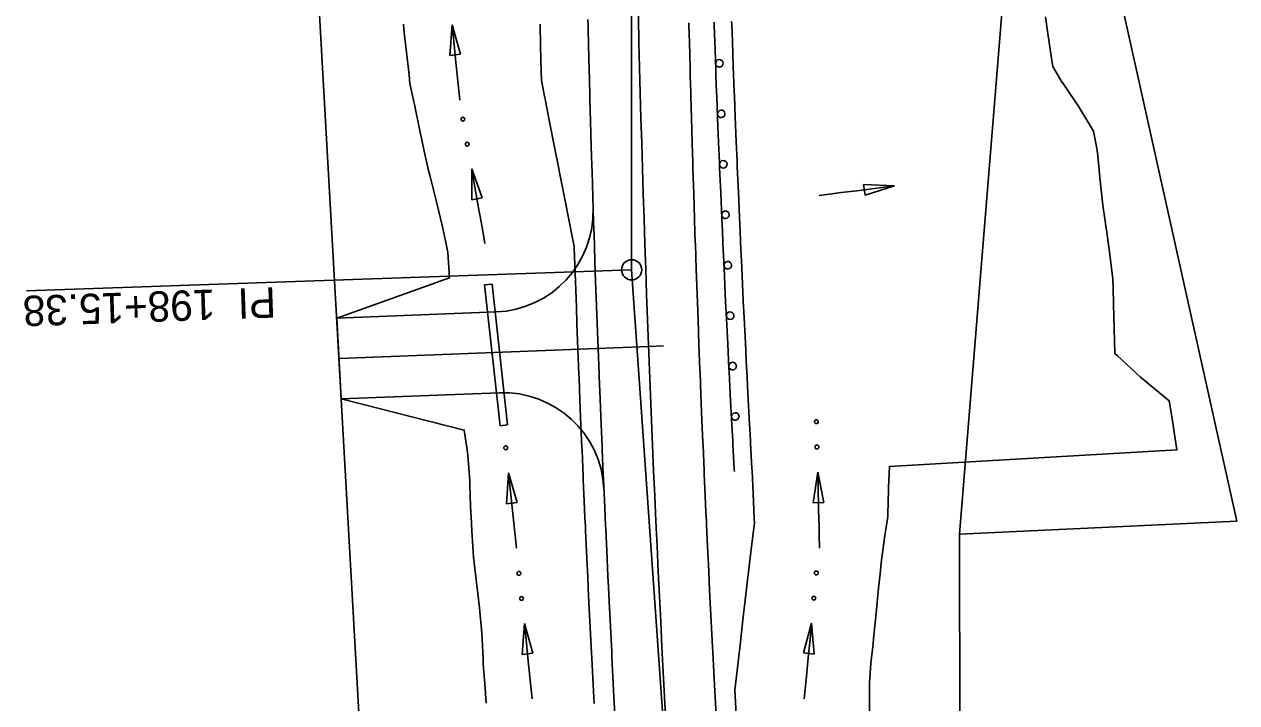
# Model space of a CAD drawing. Extents: x 1 to 1477871, y 1 to 1872901.
# Drawn here: x 1438490.8 to 1438731.1, y 1869665.9 to 1869800.2 of the extents above; entities that cross this region are included whole.
import ezdxf

# ---------------------------------------------------------------- set-up
doc = ezdxf.new("R2010")
doc.units = 0
for name, color, linetype in [('R_Drive', 7, 'Continuous'), ('R_Horz Alg', 7, 'Continuous'), ('R_Horz Alg Annot', 7, 'Continuous'), ('R_No Plot', 7, 'Continuous'), ('R_Proposed Const Limits_Cut', 7, 'Continuous'), ('R_Proposed Road_Lane', 7, 'Continuous'), ('R_Proposed Road_Shoulder', 7, 'Continuous'), ('R_ROW', 7, 'Continuous'), ('R_Steel', 7, 'Continuous'), ('R_Temp Easement', 7, 'Continuous'), ('R_Water', 7, 'Continuous')]:
    doc.layers.add(name, color=color, linetype=linetype)

msp = doc.modelspace()

# ---------------------------------------------------------------- linework, layer by layer
at = {"layer": 'R_Drive'}
for p, q in [((1438552.73, 1869742.04), (1438584.34, 1869743.25)), ((1438552.73, 1869742.04), (1438553.63, 1869726.06)), ((1438553.63, 1869726.06), (1438584.94, 1869727.26))]:
    msp.add_line(p, q, dxfattribs=at)
for centre, start, end in [((1438583.57, 1869763.23), 272.1875, 1.841), ((1438585.71, 1869707.27), 2.473, 92.1875)]:
    msp.add_arc(centre, 20, start, end, dxfattribs=at)
at = {"layer": 'R_Horz Alg'}
msp.add_arc((1443194.86, 1869911.35), 4583.66, 180, 183.99213, dxfattribs=at)
at = {"layer": 'R_Horz Alg Annot'}
for p, q in [((1438611.19, 1869751.6), (1438611.19, 1869911.35)), ((1438622.32, 1869592.24), (1438611.19, 1869751.6))]:
    msp.add_line(p, q, dxfattribs=at)
for points in [[(1438611.19, 1869751.6), (1438491.27, 1869747.42)], [(1438617.53, 1869736.51), (1438614.53, 1869736.4)]]:
    msp.add_lwpolyline(points, dxfattribs=at)
msp.add_circle((1438611.19, 1869751.6), 2, dxfattribs=at)
at = {"layer": 'R_No Plot'}
msp.add_line((1438553.26, 1869734.05), (1438614.53, 1869736.4), dxfattribs=at)
at = {"layer": 'R_Proposed Const Limits_Cut'}
for points in [[(1438658.35, 1869663.74), (1438658.32, 1869668.64), (1438658.3, 1869669.81), (1438658.62, 1869673.62), (1438659.03, 1869677.55), (1438659.15, 1869678.61), (1438659.65, 1869683.59), (1438660.13, 1869688.58), (1438660.43, 1869691.4), (1438660.66, 1869693.56), (1438661.31, 1869698.55), (1438661.93, 1869702.72), (1438661.95, 1869703.53), (1438662.01, 1869705.24), (1438662.12, 1869708.5), (1438662.26, 1869712.64), (1438719.25, 1869715.94), (1438718.53, 1869720.8), (1438718.43, 1869721.39), (1438717.73, 1869725.66), (1438712.06, 1869730.32), (1438707.46, 1869734.54), (1438706.94, 1869735.02), (1438706.84, 1869739.92), (1438706.71, 1869744.82), (1438706.62, 1869748.12), (1438706.57, 1869749.72), (1438705.97, 1869754.6), (1438705.27, 1869759.48), (1438705.23, 1869759.79), (1438704.96, 1869761.68), (1438704.58, 1869764.36), (1438704.02, 1869769.24), (1438703.55, 1869774.13), (1438703.45, 1869775.25), (1438702.71, 1869779.01), (1438699.84, 1869783.83), (1438697.1, 1869787.86), (1438696.56, 1869788.65), (1438696.54, 1869788.68), (1438694.66, 1869791.86), (1438694.38, 1869793.5), (1438693.68, 1869798.4), (1438693.21, 1869801.65)], [(1438582.38, 1869665.77), (1438582.07, 1869669.61), (1438581.79, 1869673.57), (1438581.73, 1869674.64), (1438581.47, 1869679.67), (1438581.02, 1869684.69), (1438580.73, 1869687.53), (1438580.46, 1869689.71), (1438579.82, 1869694.72), (1438579.58, 1869698.93), (1438579.53, 1869699.75), (1438579.43, 1869701.48), (1438579.24, 1869704.79), (1438579.11, 1869709), (1438579.09, 1869709.82), (1438578.71, 1869714.85), (1438578.64, 1869715.46), (1438578.02, 1869719.87), (1438553.63, 1869726.06), (1438552.73, 1869742.04), (1438575.09, 1869750.03), (1438574.76, 1869755.06), (1438574.72, 1869755.38), (1438574.29, 1869757.32), (1438573.67, 1869760.07), (1438572.51, 1869765.08), (1438571.25, 1869770.09), (1438570.96, 1869771.23), (1438570.1, 1869775.1), (1438569.02, 1869780.12), (1438568.13, 1869784.32), (1438567.95, 1869785.14), (1438567.95, 1869785.17), (1438567.25, 1869788.48), (1438567.07, 1869790.17), (1438566.5, 1869795.21), (1438566.13, 1869798.55), (1438566.07, 1869799.15), (1438565.97, 1869800.25)]]:
    msp.add_lwpolyline(points, dxfattribs=at)
at = {"layer": 'R_Proposed Road_Lane'}
for points in [[(1438608.02, 1869660.99), (1438607.75, 1869665.94), (1438607.69, 1869667.12), (1438607.49, 1869670.94), (1438607.28, 1869674.89), (1438607.23, 1869675.94), (1438606.98, 1869680.95), (1438606.73, 1869685.95), (1438606.59, 1869688.79), (1438606.48, 1869690.96), (1438606.25, 1869695.96), (1438606.05, 1869700.15), (1438606.01, 1869700.97), (1438605.94, 1869702.69), (1438605.79, 1869705.97), (1438605.6, 1869710.16), (1438605.57, 1869710.98), (1438605.35, 1869715.99), (1438605.32, 1869716.59), (1438605.14, 1869720.99), (1438604.94, 1869726), (1438604.76, 1869730.49), (1438604.74, 1869731.01), (1438604.54, 1869736.01), (1438604.35, 1869741.02), (1438604.23, 1869744.4), (1438604.17, 1869746.03), (1438603.99, 1869751.04), (1438603.82, 1869756.04), (1438603.81, 1869756.36), (1438603.74, 1869758.31), (1438603.65, 1869761.05), (1438603.49, 1869766.06), (1438603.34, 1869771.07), (1438603.3, 1869772.21), (1438603.19, 1869776.08), (1438603.04, 1869781.09), (1438602.92, 1869785.27), (1438602.9, 1869786.1), (1438602.9, 1869786.12), (1438602.81, 1869789.42), (1438602.77, 1869791.1), (1438602.64, 1869796.11), (1438602.56, 1869799.44), (1438602.54, 1869800.04), (1438602.52, 1869801.12)], [(1438627.99, 1869662.08), (1438627.73, 1869667), (1438627.66, 1869668.18), (1438627.46, 1869671.99), (1438627.26, 1869675.92), (1438627.2, 1869676.97), (1438626.95, 1869681.95), (1438626.7, 1869686.93), (1438626.56, 1869689.75), (1438626.46, 1869691.92), (1438626.22, 1869696.9), (1438626.03, 1869701.07), (1438625.99, 1869701.88), (1438625.92, 1869703.59), (1438625.77, 1869706.87), (1438625.58, 1869711.04), (1438625.55, 1869711.85), (1438625.33, 1869716.84), (1438625.31, 1869717.44), (1438625.12, 1869721.82), (1438624.92, 1869726.81), (1438624.74, 1869731.28), (1438624.72, 1869731.79), (1438624.53, 1869736.78), (1438624.34, 1869741.76), (1438624.22, 1869745.12), (1438624.16, 1869746.75), (1438623.98, 1869751.73), (1438623.81, 1869756.72), (1438623.8, 1869757.04), (1438623.73, 1869758.97), (1438623.64, 1869761.71), (1438623.48, 1869766.69), (1438623.33, 1869771.68), (1438623.29, 1869772.82), (1438623.18, 1869776.67), (1438623.03, 1869781.65), (1438622.92, 1869785.82), (1438622.89, 1869786.64), (1438622.89, 1869786.67), (1438622.8, 1869789.95), (1438622.76, 1869791.63), (1438622.63, 1869796.62), (1438622.55, 1869799.93), (1438622.54, 1869800.52)]]:
    msp.add_lwpolyline(points, dxfattribs=at)
at = {"layer": 'R_Proposed Road_Shoulder'}
for points in [[(1438603.76, 1869665.72), (1438603.7, 1869666.9), (1438603.5, 1869670.73), (1438603.29, 1869674.68), (1438603.24, 1869675.74), (1438602.98, 1869680.75), (1438602.73, 1869685.76), (1438602.59, 1869688.59), (1438602.49, 1869690.77), (1438602.25, 1869695.78), (1438602.06, 1869699.96), (1438602.02, 1869700.79), (1438601.94, 1869702.5), (1438601.79, 1869705.79), (1438601.61, 1869709.98), (1438601.57, 1869710.8), (1438601.35, 1869715.82), (1438601.33, 1869716.42), (1438601.14, 1869720.83), (1438600.94, 1869725.84), (1438600.76, 1869730.33), (1438600.74, 1869730.85), (1438600.54, 1869735.86), (1438600.35, 1869740.87), (1438600.23, 1869744.25), (1438600.17, 1869745.88), (1438599.99, 1869750.9), (1438599.82, 1869755.91), (1438599.81, 1869756.23), (1438599.42, 1869758.16), (1438598.88, 1869760.9), (1438597.88, 1869765.88), (1438596.89, 1869770.87), (1438596.67, 1869772.01), (1438595.91, 1869775.86), (1438594.93, 1869780.86), (1438594.12, 1869785.03), (1438593.96, 1869785.85), (1438593.95, 1869785.88), (1438593.32, 1869789.17), (1438593.27, 1869790.86), (1438593.14, 1869795.88), (1438593.04, 1869800.21)], [(1438635.05, 1869711.85), (1438635.03, 1869712.27), (1438634.76, 1869717.24), (1438634.73, 1869717.83), (1438634.49, 1869722.21), (1438634.23, 1869727.18), (1438634, 1869731.64), (1438633.98, 1869732.16), (1438633.73, 1869737.13), (1438633.48, 1869742.1), (1438633.32, 1869745.46), (1438633.24, 1869747.07), (1438633.01, 1869752.05), (1438632.78, 1869757.02), (1438632.77, 1869757.34), (1438632.68, 1869759.27), (1438632.56, 1869762), (1438632.34, 1869766.97), (1438632.13, 1869771.95), (1438632.08, 1869773.09), (1438631.92, 1869776.92), (1438631.72, 1869781.9), (1438631.56, 1869786.06), (1438631.53, 1869786.88), (1438631.52, 1869786.91), (1438631.4, 1869790.18), (1438631.33, 1869791.85), (1438631.15, 1869796.83), (1438631.03, 1869800.13), (1438631.01, 1869800.73)], [(1438631.99, 1869662.3), (1438631.72, 1869667.22), (1438631.66, 1869668.39), (1438632.09, 1869672.23), (1438632.54, 1869676.19), (1438632.67, 1869677.25), (1438633.25, 1869682.27), (1438633.83, 1869687.28), (1438634.17, 1869690.12), (1438634.42, 1869692.3), (1438635.02, 1869697.31), (1438635.52, 1869701.5), (1438635.48, 1869702.32), (1438635.41, 1869704.03), (1438635.26, 1869707.29), (1438635.06, 1869711.85)]]:
    msp.add_lwpolyline(points, dxfattribs=at)
at = {"layer": 'R_ROW'}
for p, q in [((1438587.34, 1869127.27), (1438531.34, 1870121.98)), ((1438701.19, 1870006.35), (1438676.17, 1869699.24)), ((1438676.17, 1869699.24), (1438677.33, 1869126.48))]:
    msp.add_line(p, q, dxfattribs=at)
at = {"layer": 'R_Steel'}
msp.add_lwpolyline([(1438631.56, 1869711.66), (1438631.53, 1869712.07), (1438631.26, 1869717.05), (1438631.23, 1869717.65), (1438631, 1869722.02), (1438630.73, 1869727), (1438630.51, 1869731.47), (1438630.48, 1869731.98), (1438630.23, 1869736.95), (1438629.98, 1869741.93), (1438629.82, 1869745.29), (1438629.74, 1869746.91), (1438629.51, 1869751.89), (1438629.28, 1869756.86), (1438629.27, 1869757.18), (1438629.18, 1869759.11), (1438629.06, 1869761.85), (1438628.84, 1869766.82), (1438628.63, 1869771.8), (1438628.58, 1869772.94), (1438628.42, 1869776.78), (1438628.22, 1869781.76), (1438628.06, 1869785.92), (1438628.03, 1869786.69), (1438628.03, 1869786.72), (1438627.9, 1869790.05), (1438627.84, 1869791.72), (1438627.65, 1869796.7), (1438627.53, 1869800.01), (1438627.51, 1869800.6)], dxfattribs=at)
for centre, major_axis in [((1438628.56, 1869792.46), (-0.491, -0.567)), ((1438628.94, 1869782.47), (-0.49, -0.568)), ((1438629.35, 1869772.48), (-0.489, -0.569)), ((1438629.78, 1869762.49), (-0.488, -0.57)), ((1438630.23, 1869752.5), (-0.486, -0.571)), ((1438630.71, 1869742.52), (-0.485, -0.572)), ((1438631.2, 1869732.53), (-0.484, -0.573)), ((1438631.72, 1869722.54), (-0.482, -0.574))]:
    msp.add_ellipse(centre, major_axis=major_axis, ratio=0.998743, dxfattribs=at)
at = {"layer": 'R_Temp Easement'}
for q in [(1438691.05, 1869881.87), (1438676.17, 1869699.24)]:
    msp.add_line((1438731.11, 1869701.82), q, dxfattribs=at)
at = {"layer": 'R_Water'}
for p, q in [((1438575.63, 1869800.12), (1438575.17, 1869794.05)), ((1438577.28, 1869794.26), (1438575.63, 1869800.12)), ((1438575.17, 1869794.05), (1438577.28, 1869794.26)), ((1438579.51, 1869771.56), (1438579.5, 1869765.46)), ((1438581.59, 1869765.83), (1438579.51, 1869771.56)), ((1438663.26, 1869768.2), (1438657.17, 1869768.5)), ((1438657.17, 1869768.5), (1438657.44, 1869766.4)), ((1438657.44, 1869766.4), (1438663.26, 1869768.2)), ((1438579.5, 1869765.46), (1438581.59, 1869765.83)), ((1438582.04, 1869748.61), (1438583.53, 1869748.77)), ((1438582.04, 1869748.61), (1438585.1, 1869720.73)), ((1438583.53, 1869748.77), (1438586.59, 1869720.89)), ((1438586.59, 1869720.89), (1438585.1, 1869720.73)), ((1438586.8, 1869711.37), (1438586.39, 1869705.29)), ((1438588.49, 1869705.52), (1438586.8, 1869711.37)), ((1438648.07, 1869711.5), (1438647.15, 1869705.48)), ((1438649.27, 1869705.53), (1438648.07, 1869711.5)), ((1438586.39, 1869705.29), (1438588.49, 1869705.52)), ((1438647.15, 1869705.48), (1438649.27, 1869705.53)), ((1438589.93, 1869681.54), (1438589.5, 1869675.46)), ((1438591.61, 1869675.68), (1438589.93, 1869681.54)), ((1438646.85, 1869681.6), (1438645.22, 1869675.73)), ((1438647.33, 1869675.52), (1438646.85, 1869681.6)), ((1438589.5, 1869675.46), (1438591.61, 1869675.68)), ((1438645.22, 1869675.73), (1438647.33, 1869675.52))]:
    msp.add_line(p, q, dxfattribs=at)
for points in [[(1438577.13, 1869785.2), (1438576.87, 1869787.7), (1438576.68, 1869789.58), (1438576.37, 1869792.66), (1438575.88, 1869797.62), (1438575.63, 1869800.12)], [(1438582.1, 1869756.78), (1438581.67, 1869759.26), (1438581.34, 1869761.12), (1438580.8, 1869764.17), (1438579.94, 1869769.08), (1438579.51, 1869771.56)], [(1438648.38, 1869766.31), (1438650.87, 1869766.63), (1438652.74, 1869766.87), (1438655.82, 1869767.26), (1438660.76, 1869767.88), (1438663.26, 1869768.2)], [(1438588.4, 1869696.46), (1438588.13, 1869698.96), (1438587.93, 1869700.84), (1438587.6, 1869703.92), (1438587.07, 1869708.87), (1438586.8, 1869711.37)], [(1438648.43, 1869696.51), (1438648.37, 1869699.03), (1438648.32, 1869700.91), (1438648.25, 1869704.01), (1438648.13, 1869708.99), (1438648.07, 1869711.5)], [(1438591.5, 1869666.62), (1438591.23, 1869669.12), (1438591.04, 1869671), (1438590.71, 1869674.08), (1438590.19, 1869679.04), (1438589.93, 1869681.54)], [(1438645.41, 1869666.67), (1438645.65, 1869669.17), (1438645.83, 1869671.05), (1438646.13, 1869674.13), (1438646.61, 1869679.09), (1438646.85, 1869681.6)]]:
    msp.add_lwpolyline(points, dxfattribs=at)
for centre in [(1438577.75, 1869781.42), (1438578.61, 1869776.48), (1438647.8, 1869721.52), (1438586.23, 1869716.35), (1438647.91, 1869716.51), (1438588.85, 1869691.49), (1438647.79, 1869691.57), (1438589.37, 1869686.51), (1438647.3, 1869686.58)]:
    msp.add_circle(centre, 0.375, dxfattribs=at)

# ---------------------------------------------------------------- texts
at = {"layer": 'R_Horz Alg Annot'}
msp.add_text('PI  198+15.38', height=6, rotation=181.9961, dxfattribs=at).set_placement((1438540.59, 1869748.14))

doc.saveas('drawing.dxf')
